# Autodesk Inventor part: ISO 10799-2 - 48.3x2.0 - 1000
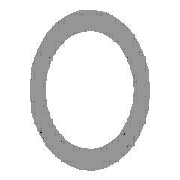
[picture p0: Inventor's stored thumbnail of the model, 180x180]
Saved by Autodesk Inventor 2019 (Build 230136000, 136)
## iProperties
Created: 2018-07
Part Number: ISO 10799-2 - 48.3x2.0 - 1000
Material: Acier, doux
Description: Aciers de construction - Coupes creuses profilées formées à froid, soudées
Document SubType Name: Modeling
Standard: ISO
Designer: Fabian Perrée
Standard Revision: First edition 2011-09-15
Standards Organization: ISO
Language: fr-FR
Size Designation: 48.3x2.0
Categories: <MemberInstance><Categories><Category DisplayName="Profilés" InternalName="089c4875-fa83-4c05-b084-43b9cc11f5ed" Mnemonic="GRDR"><CategoryParameter DisplayName=
Stock Number: 48.3x2.0
Density: 7.85 g/cm^3
Appearance: Semi-poli
IsCustomPart: 1
_CCFamilyMember: 14
_CCFamilyDisplayName: ISO 10799-2 (Profils creux circulaires - Formés à froid) - Aciers de construction - Coupes creuses profilées formées à froid, soudées
_FrameMemberDoc: Frame Member File
_Version: 15.0.0
_GetPNFromCC: 1
Author: Fabian Perrée
G_L: 1000,000 mm
G_W: 48,300 mm
G_H: 48,300 mm
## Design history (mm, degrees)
node "Plan de départ"
node "Plan de fin"
sketch "Esquisse"
  geometry: C1 r 22.15 at (0, 0); C2 r 24.15 at (0, 0); 2 further points
  constraints: 3 coincident, 2 centre point
  dimensions: "d0" = 48.3 diameter of C2 (= G_H); "d1" = 2 radial gap between concentric circles of C2 C1 (= G_T)
extrude "Corps" new body sketch "Esquisse" stored distance "d2" = 1000 (= G_L); taper "d3" = 0 deg
node "Driven Length"
  sketch "Sketch3"
    geometry: L1 (0, 0)-(10, 0) reference
    constraints: 2 end point, 1 horizontal
  workplane "Work Plane3"
  sketch "Sketch4"
    geometry: L1 (-2, 0)-(12, 0) reference; L2 (-2, 1000)-(12, 1000) reference
    dimensions: "d7" = 1000 distance between parallel lines of L1 L2 (derived)
body "Solid1"
other parameters: "G_H" = 48.3 [user parameter; used in 1 equation term], "G_T" = 2 [user parameter; used in 1 equation term], "G_L" = 1000 (= d7) [user parameter; used in 1 equation term], "G_OFFSET_START" = 0 [user parameter; used in 1 equation term], "G_OFFSET_END" = 0 [user parameter; used in 1 equation term], "d4" = 0 (computed from G_OFFSET_START), "d6" = 90 deg, "MAS" = 0.228 [user parameter]
